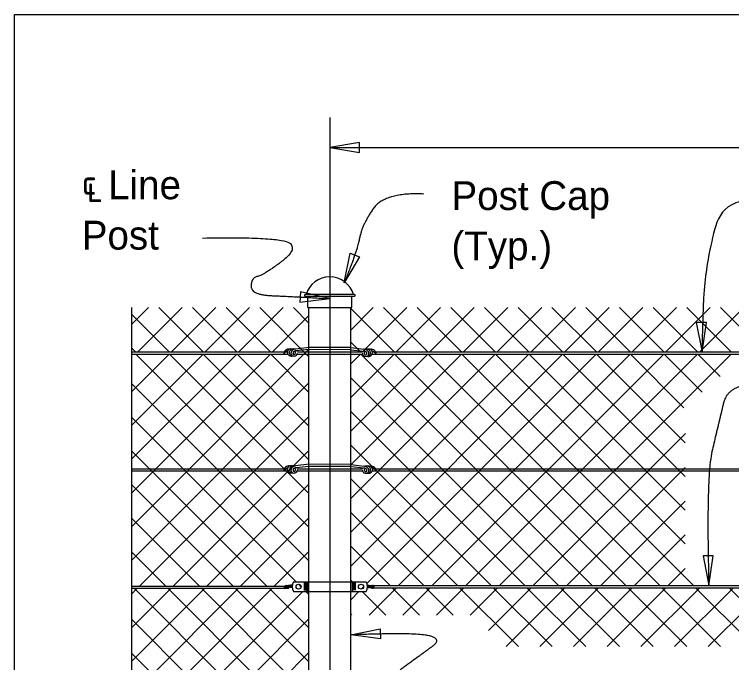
# Model space of a CAD drawing. Extents: x 0 to 41.1, y 0 to 26.4.
# Drawn here: x 0 to 5.02, y 21.87 to 26.4 of the extents above; entities that cross this region are included whole.
import ezdxf

# ---------------------------------------------------------------- set-up
doc = ezdxf.new("R2010")
doc.units = 0
for name, color, linetype in [('CL_Major', 7, 'Continuous'), ('Dimension', 7, 'Continuous'), ('Miscellaneous', 7, 'Continuous'), ('Miscellaneous1', 7, 'Continuous'), ('SteelMisc', 7, 'Continuous'), ('SteelMisc_h', 7, 'Continuous')]:
    doc.layers.add(name, color=color, linetype=linetype)

msp = doc.modelspace()

# ---------------------------------------------------------------- linework, layer by layer
at = {"layer": 'CL_Major'}
msp.add_line((2.2062, 25.6784), (2.2062, 14.8533), dxfattribs=at)
at = {"layer": 'Dimension'}
msp.add_line((2.2062, 25.4682), (22.2062, 25.4682), dxfattribs=at)
for points in [[(2.2062, 25.4682), (2.4145, 25.4329), (2.4145, 25.5035)], [(2.3061, 24.523), (2.3482, 24.73), (2.414, 24.7046)], [(2.2062, 24.4121), (2.0002, 24.4587), (1.9964, 24.3882)], [(4.8088, 24.0365), (4.8396, 24.2455), (4.769, 24.244)], [(4.8566, 22.4048), (4.8874, 22.6138), (4.8169, 22.6123)], [(2.3519, 22.0601), (2.5585, 22.1039), (2.5614, 22.0334)]]:
    msp.add_lwpolyline(points, close=True, dxfattribs=at)
msp.add_lwpolyline([(0.8194, 24.349), (0.8194, 21.1819), (0.9227, 21.1819), (0.8194, 21.1369), (0.716, 21.0919), (0.8194, 21.0919), (0.8194, 20.1983)], dxfattribs=at)
for points, degree in [([(2.8646, 25.1435), (2.5898, 25.1563), (2.4301, 24.926), (2.3965, 24.7387), (2.3061, 24.523)], 2), ([(5.2657, 25.0995), (4.9524, 25.1279), (4.8838, 24.8459), (4.8116, 24.5363), (4.8088, 24.0365)], 3), ([(1.3167, 24.8359), (1.8625, 24.8457), (1.9849, 24.7568), (1.7407, 24.5755), (1.6559, 24.5571), (1.6559, 24.4393), (1.9339, 24.427), (2.2062, 24.4121)], 2), ([(5.3115, 23.815), (4.9982, 23.8433), (4.9198, 23.5211), (4.8367, 23.1628), (4.8566, 22.4048)], 2), ([(3.2402, 21.7554), (3.0279, 21.7554), (2.6079, 21.7554), (2.8581, 21.9325), (2.9953, 22.0352), (2.7847, 22.0777), (2.352, 22.06)], 2)]:
    msp.add_open_spline(points, degree=degree, dxfattribs=at)
at = {"layer": 'Miscellaneous'}
for p, q in [((0.9371, 24.349), (0.8194, 24.2313)), ((1.1728, 24.349), (0.8602, 24.0365)), ((1.3218, 24.0365), (1.0093, 24.349)), ((1.4085, 24.349), (1.0959, 24.0365)), ((1.5575, 24.0365), (1.245, 24.349)), ((1.6442, 24.349), (1.3316, 24.0365)), ((1.7932, 24.0365), (1.4807, 24.349)), ((1.8799, 24.349), (1.5674, 24.0365)), ((2.0603, 24.0051), (1.7164, 24.349)), ((2.0603, 24.2408), (1.9521, 24.349)), ((2.658, 24.0365), (2.3455, 24.349)), ((2.509, 24.349), (2.352, 24.1921)), ((2.7447, 24.349), (2.4321, 24.0365)), ((2.8937, 24.0365), (2.5812, 24.349)), ((2.9804, 24.349), (2.6678, 24.0365)), ((3.1294, 24.0365), (2.8169, 24.349)), ((3.2161, 24.349), (2.9035, 24.0365)), ((3.3651, 24.0365), (3.0526, 24.349)), ((3.4518, 24.349), (3.1392, 24.0365)), ((3.6008, 24.0365), (3.2883, 24.349)), ((3.6875, 24.349), (3.3749, 24.0365)), ((3.8365, 24.0365), (3.524, 24.349)), ((3.9232, 24.349), (3.6106, 24.0365)), ((4.0722, 24.0365), (3.7597, 24.349)), ((4.1589, 24.349), (3.8463, 24.0365)), ((4.3079, 24.0365), (3.9954, 24.349)), ((4.3946, 24.349), (4.082, 24.0365)), ((4.5436, 24.0365), (4.2311, 24.349)), ((4.6303, 24.349), (4.3177, 24.0365)), ((4.7793, 24.0365), (4.4668, 24.349)), ((4.866, 24.349), (4.5535, 24.0365)), ((5.015, 24.0365), (4.7025, 24.349)), ((5.1017, 24.349), (4.7948, 24.0422)), ((5.2507, 24.0365), (4.9382, 24.349)), ((1.0861, 24.0365), (0.8194, 24.3033)), ((2.0603, 24.2938), (1.8031, 24.0365)), ((2.4223, 24.0365), (2.352, 24.1068)), ((2.0603, 24.0581), (0.8192, 22.817)), ((0.8504, 24.0365), (0.8194, 24.0676)), ((1.9047, 24.0365), (1.9002, 24.041)), ((1.7883, 24.0218), (0.8192, 23.0527)), ((1.5526, 24.0218), (0.8192, 23.2884)), ((1.3169, 24.0218), (0.8192, 23.5241)), ((1.0812, 24.0218), (0.8192, 23.7598)), ((2.0603, 22.8138), (0.8524, 24.0218)), ((2.0603, 23.0495), (1.0881, 24.0218)), ((2.0603, 23.2852), (1.3238, 24.0218)), ((2.0603, 23.5209), (1.5595, 24.0218)), ((2.0603, 23.7566), (1.7952, 24.0218)), ((3.8316, 24.0218), (2.352, 22.5421)), ((3.5959, 24.0218), (2.352, 22.7779)), ((3.3602, 24.0218), (2.352, 23.0136)), ((3.1245, 24.0218), (2.352, 23.2493)), ((2.8888, 24.0218), (2.352, 23.485)), ((2.6531, 24.0218), (2.352, 23.7207)), ((2.4174, 24.0218), (2.352, 23.9564)), ((4.0413, 22.4048), (2.4243, 24.0218)), ((4.0673, 24.0218), (2.4652, 22.4196)), ((4.277, 22.4048), (2.66, 24.0218)), ((4.303, 24.0218), (2.686, 22.4048)), ((4.5127, 22.4048), (2.8957, 24.0218)), ((4.5387, 24.0218), (2.9217, 22.4048)), ((4.7484, 22.4048), (3.1314, 24.0218)), ((4.7744, 24.0218), (3.1574, 22.4048)), ((4.6913, 22.6976), (3.3671, 24.0218)), ((5.0101, 24.0218), (3.3931, 22.4048)), ((4.6913, 22.9333), (3.6028, 24.0218)), ((4.6913, 23.169), (3.8385, 24.0218)), ((4.6913, 23.4047), (4.0742, 24.0218)), ((4.6827, 23.649), (4.3099, 24.0218)), ((4.8094, 23.758), (4.5456, 24.0218)), ((4.936, 23.8671), (4.7813, 24.0218)), ((3.8056, 22.4048), (2.352, 23.8583)), ((2.0603, 23.8224), (0.8192, 22.5813)), ((2.0603, 22.5781), (0.8194, 23.8191)), ((1.9708, 22.4319), (0.8194, 23.5834)), ((2.0603, 23.5867), (0.8745, 22.4009)), ((3.5699, 22.4048), (2.352, 23.6226)), ((4.6938, 23.4697), (3.6288, 22.4048)), ((3.3342, 22.4048), (2.352, 23.3869)), ((1.7662, 22.4009), (0.8194, 23.3477)), ((2.0603, 23.351), (1.1102, 22.4009)), ((4.6913, 23.2315), (3.8645, 22.4048)), ((1.9048, 23.219), (1.9004, 23.2235)), ((3.0985, 22.4048), (2.352, 23.1512)), ((1.5305, 22.4009), (0.8194, 23.112)), ((2.0603, 23.1153), (1.3459, 22.4009)), ((4.6913, 22.9958), (4.1002, 22.4048)), ((1.2948, 22.4009), (0.8194, 22.8763)), ((2.0603, 22.8796), (1.5816, 22.4009)), ((2.8628, 22.4048), (2.352, 22.9155)), ((4.6913, 22.7601), (4.3359, 22.4048)), ((2.6271, 22.4048), (2.352, 22.6798)), ((1.0591, 22.4009), (0.8194, 22.6406)), ((2.0603, 22.6439), (1.8173, 22.4009)), ((4.6913, 22.5244), (4.5716, 22.4048)), ((2.3642, 22.4319), (2.352, 22.4441)), ((0.8234, 22.4009), (0.8192, 22.405)), ((1.8028, 22.3863), (0.8192, 21.4028)), ((1.0955, 22.3862), (0.8192, 22.1099)), ((1.3313, 22.3862), (0.8192, 21.8742)), ((1.567, 22.3862), (0.8192, 21.6385)), ((0.8598, 22.3861), (0.8192, 22.3456)), ((2.0603, 21.1639), (0.8381, 22.3861)), ((2.0603, 21.3996), (1.0738, 22.3862)), ((2.0603, 21.6353), (1.3094, 22.3862)), ((2.0603, 21.871), (1.5451, 22.3862)), ((2.0559, 22.1112), (1.7808, 22.3863)), ((2.0058, 22.3969), (1.9883, 22.4144)), ((2.4419, 22.3963), (2.426, 22.3805)), ((2.6712, 22.39), (2.4806, 22.1994)), ((2.8325, 22.1994), (2.6418, 22.39)), ((2.9069, 22.39), (2.7163, 22.1994)), ((3.0682, 22.1994), (2.8775, 22.39)), ((3.1427, 22.39), (2.952, 22.1994)), ((3.5244, 21.9789), (3.1132, 22.39)), ((3.3784, 22.39), (3.1877, 22.1994)), ((3.6141, 22.39), (3.3156, 22.0916)), ((3.7601, 21.9789), (3.3489, 22.39)), ((3.8498, 22.39), (3.4386, 21.9789)), ((3.9958, 21.9789), (3.5846, 22.39)), ((4.0855, 22.39), (3.6743, 21.9789)), ((4.2315, 21.9789), (3.8203, 22.39)), ((4.3212, 22.39), (3.91, 21.9789)), ((4.4672, 21.9789), (4.056, 22.39)), ((4.5569, 22.39), (4.1457, 21.9789)), ((4.7029, 21.9789), (4.2917, 22.39)), ((4.7926, 22.39), (4.3814, 21.9789)), ((4.9386, 21.9789), (4.5274, 22.39)), ((5.0283, 22.39), (4.6171, 21.9789)), ((5.1743, 21.9789), (4.7631, 22.39)), ((5.264, 22.39), (4.8528, 21.9789)), ((7.2458, 20.143), (4.9988, 22.39)), ((2.0163, 22.3642), (0.8341, 21.1819)), ((2.0603, 22.3424), (2.0386, 22.3642)), ((2.4097, 22.3642), (2.352, 22.3064)), ((2.5968, 22.1994), (2.432, 22.3642)), ((2.0603, 22.1725), (0.8192, 20.9314)), ((2.3611, 22.1994), (2.352, 22.2084)), ((2.0603, 20.9282), (0.8192, 22.1693)), ((2.0603, 21.9368), (0.8192, 20.6957)), ((2.0603, 20.6925), (0.8192, 21.9336))]:
    msp.add_line(p, q, dxfattribs=at)
at = {"layer": 'Miscellaneous1'}
msp.add_lwpolyline([(0, 26.4), (41.0667, 26.4), (41.0667, 0), (0, 0)], close=True, dxfattribs=at)
at = {"layer": 'SteelMisc'}
for p, q in [((2.3786, 24.441), (2.0339, 24.441)), ((2.0339, 24.4288), (2.3786, 24.4288)), ((2.0521, 24.349), (2.0521, 24.4288)), ((2.3603, 24.349), (2.3603, 24.4288)), ((2.0521, 24.349), (2.3603, 24.349)), ((2.0603, 17.8646), (2.0603, 24.349)), ((2.352, 17.8646), (2.352, 24.349)), ((1.8858, 24.0365), (0.8192, 24.0365)), ((1.9095, 24.0365), (1.8943, 24.0365)), ((2.0608, 24.0708), (1.9665, 24.0597)), ((2.0608, 24.0563), (1.9686, 24.0469)), ((2.0603, 24.0365), (1.9799, 24.0365)), ((2.3519, 24.0691), (2.0608, 24.0708)), ((2.3519, 24.0546), (2.0608, 24.0563)), ((2.3519, 24.0691), (2.4468, 24.058)), ((2.3519, 24.0546), (2.4445, 24.0451)), ((2.4341, 24.0365), (2.3519, 24.0365)), ((2.5172, 24.0365), (2.504, 24.0365)), ((11.9229, 24.0365), (2.5271, 24.0365)), ((1.9144, 24.0218), (0.8192, 24.0218)), ((2.0603, 24.0218), (1.9772, 24.0218)), ((2.4355, 24.0218), (2.3519, 24.0218)), ((11.9243, 24.0218), (2.5005, 24.0218)), ((2.0609, 23.2533), (1.9666, 23.2422)), ((2.0609, 23.2388), (1.9688, 23.2294)), ((2.3521, 23.2516), (2.0609, 23.2533)), ((2.3521, 23.2371), (2.0609, 23.2388)), ((2.3521, 23.2516), (2.447, 23.2405)), ((2.3521, 23.2371), (2.4447, 23.2276)), ((1.886, 23.219), (0.8194, 23.219)), ((1.9146, 23.2043), (0.8194, 23.2043)), ((1.9097, 23.219), (1.8945, 23.219)), ((2.0604, 23.2043), (1.9774, 23.2043)), ((2.0604, 23.219), (1.98, 23.219)), ((2.4343, 23.219), (2.3521, 23.219)), ((2.4357, 23.2043), (2.3521, 23.2043)), ((11.9244, 23.2043), (2.5006, 23.2043)), ((2.5173, 23.219), (2.5042, 23.219)), ((11.9231, 23.219), (2.5273, 23.219)), ((1.9522, 22.4319), (2.4601, 22.4319)), ((2.0466, 22.3642), (2.0466, 22.4319)), ((2.0504, 22.3642), (2.0504, 22.4319)), ((2.3657, 22.3642), (2.3657, 22.4319)), ((0.8194, 22.4009), (1.8897, 22.4009)), ((0.8194, 22.3861), (1.916, 22.3863)), ((1.9443, 22.389), (1.9104, 22.3947)), ((1.9439, 22.3938), (1.9137, 22.3987)), ((1.9449, 22.4094), (1.9182, 22.405)), ((1.9442, 22.4044), (1.9182, 22.4002)), ((1.9352, 22.403), (1.9352, 22.3951)), ((2.0236, 22.4211), (2.0466, 22.4211)), ((2.0236, 22.4155), (2.0466, 22.4155)), ((2.0236, 22.4075), (2.0466, 22.4075)), ((2.0236, 22.402), (2.0466, 22.402)), ((2.0236, 22.394), (2.0466, 22.394)), ((2.0236, 22.3884), (2.0466, 22.3884)), ((2.0236, 22.3804), (2.0466, 22.3804)), ((2.0236, 22.3749), (2.0466, 22.3749)), ((2.3886, 22.4211), (2.3657, 22.4211)), ((2.3886, 22.4155), (2.3657, 22.4155)), ((2.3886, 22.4075), (2.3657, 22.4075)), ((2.3886, 22.402), (2.3657, 22.402)), ((2.3886, 22.394), (2.3657, 22.394)), ((2.3886, 22.3884), (2.3657, 22.3884)), ((2.3886, 22.3804), (2.3657, 22.3804)), ((2.3886, 22.3749), (2.3657, 22.3749)), ((2.4674, 22.4094), (2.4967, 22.4048)), ((2.468, 22.389), (2.5017, 22.3946)), ((2.4681, 22.4044), (2.4942, 22.4003)), ((2.4684, 22.3937), (2.4983, 22.3987)), ((2.477, 22.4029), (2.477, 22.3951)), ((2.5108, 22.4048), (11.8852, 22.4048)), ((2.5141, 22.39), (11.9118, 22.39)), ((1.9524, 22.3642), (2.4597, 22.3642))]:
    msp.add_line(p, q, dxfattribs=at)
for centre, start, end in [((2.034, 24.4347), 91.1647, 268.8353), ((2.3783, 24.4347), 271.1647, 88.8353)]:
    msp.add_arc(centre, 0.00613, start, end, dxfattribs=at)
for centre, major_axis, ratio, start_param, end_param in [((2.2054, 24.4), (-0.1711, 0), 0.957868, 3.394611, 6.030583), ((1.9208, 24.024), (0.0373, 0), 0.957868, 1.486836, 3.108042), ((1.9419, 23.9843), (-0.0724, 0), 0.957868, 5.162149, 5.652106), ((1.9344, 24.036), (-0.0249, 0), 0.957868, 6.009018, 7.089857), ((1.9333, 24.0385), (0.023, 0), 0.957868, 1.29026, 2.970541), ((1.952, 24.0331), (0.0295, 0), 0.957868, 1.220941, 4.039556), ((1.9655, 24.0349), (-0.0303, -0.0108), 0.724765, 4.35367, 6.324556), ((1.9622, 24.0308), (-0.0139, 0), 0.957868, 5.22362, 6.905413), ((1.9565, 24.0284), (-0.00795, 0), 0.957868, 6.140374, 9.314262), ((1.9706, 24.022), (-0.0259, 0), 0.957868, 4.777514, 5.62749), ((1.9548, 24.0342), (0.0119, 0), 0.957868, 5.725876, 7.416677), ((1.9548, 24.0342), (0.0119, 0), 0.957868, 5.639684, 5.723117), ((1.9551, 24.033), (0.0251, 0), 0.957868, 5.531357, 6.227833), ((1.9551, 24.033), (0.0251, 0), 0.957868, 0.407687, 0.609214), ((2.4586, 24.0312), (-0.0251, 0), 0.957868, 0.055352, 0.751829), ((2.4586, 24.0312), (-0.0251, 0), 0.957868, 5.673972, 5.875498), ((2.4481, 24.0331), (0.0303, -0.0108), 0.724765, 6.241815, 8.212701), ((2.4431, 24.0202), (0.0259, 0), 0.957868, 0.655696, 1.505671), ((2.4588, 24.0325), (-0.0119, 0), 0.957868, 5.149694, 6.840495), ((2.4571, 24.0267), (0.00795, 0), 0.957868, 3.252108, 6.425997), ((2.4616, 24.0313), (-0.0295, 0), 0.957868, 2.243629, 5.062245), ((2.4514, 24.029), (0.0139, 0), 0.957868, 5.660958, 7.342751), ((2.4803, 24.0367), (-0.023, 0), 0.957868, 3.312645, 4.992926), ((2.4928, 24.0222), (-0.0373, 0), 0.957868, 3.175144, 4.79635), ((2.4792, 24.0342), (0.0249, 0), 0.957868, 5.476514, 6.557353), ((2.4717, 23.9825), (0.0724, 0), 0.957868, 0.631079, 1.121037), ((1.9358, 24.032), (0.0231, 0), 0.957868, 3.779554, 4.879821), ((1.9419, 24.0263), (0.0206, -0.0021), 0.798607, 4.32653, 5.220153), ((1.9554, 24.0263), (0.0206, -0.0021), 0.798607, 3.333154, 5.220153), ((1.948, 24.045), (0.0391, 0), 0.957868, 5.082588, 5.41974), ((2.4656, 24.0433), (-0.0391, 0), 0.957868, 0.863445, 1.200597), ((2.4588, 24.0325), (-0.0119, 0), 0.957868, 0.560069, 0.643501), ((2.4582, 24.0245), (-0.0206, -0.0021), 0.798607, 1.063032, 2.950031), ((2.4717, 24.0245), (-0.0206, -0.0021), 0.798607, 1.063032, 1.956656), ((2.4778, 24.0302), (-0.0231, 0), 0.957868, 1.403365, 2.503632), ((1.921, 23.2065), (0.0373, 0), 0.957868, 1.486836, 3.108042), ((1.9421, 23.1668), (-0.0724, 0), 0.957868, 5.162149, 5.652106), ((1.9346, 23.2185), (-0.0249, 0), 0.957868, 6.009018, 7.089857), ((1.9335, 23.221), (0.023, 0), 0.957868, 1.29026, 2.970541), ((1.9522, 23.2156), (0.0295, 0), 0.957868, 1.220941, 4.039556), ((1.9657, 23.2174), (-0.0303, -0.0108), 0.724765, 4.35367, 6.324556), ((1.9624, 23.2134), (-0.0139, 0), 0.957868, 5.22362, 6.905413), ((1.9707, 23.2045), (-0.0259, 0), 0.957868, 4.777514, 5.62749), ((1.955, 23.2168), (0.0119, 0), 0.957868, 5.725876, 7.416677), ((1.9552, 23.2155), (0.0251, 0), 0.957868, 0.407687, 0.609214), ((2.4588, 23.2138), (-0.0251, 0), 0.957868, 5.673972, 5.875498), ((2.4433, 23.2027), (0.0259, 0), 0.957868, 0.655696, 1.505671), ((2.4483, 23.2157), (0.0303, -0.0108), 0.724765, 6.241815, 8.212701), ((2.459, 23.215), (-0.0119, 0), 0.957868, 5.149694, 6.840495), ((2.4618, 23.2139), (-0.0295, 0), 0.957868, 2.243629, 5.062245), ((2.4805, 23.2192), (-0.023, 0), 0.957868, 3.312645, 4.992926), ((2.493, 23.2048), (-0.0373, 0), 0.957868, 3.175144, 4.79635), ((2.4719, 23.1651), (0.0724, 0), 0.957868, 0.631079, 1.121037), ((1.936, 23.2145), (0.0231, 0), 0.957868, 3.779554, 4.879821), ((1.9421, 23.2088), (0.0206, -0.0021), 0.798607, 4.32653, 5.220153), ((1.9556, 23.2088), (0.0206, -0.0021), 0.798607, 3.333154, 5.220153), ((1.9567, 23.211), (-0.00795, 0), 0.957868, 6.140374, 9.314262), ((1.9482, 23.2276), (0.0391, 0), 0.957868, 5.082588, 5.41974), ((1.955, 23.2168), (0.0119, 0), 0.957868, 5.639684, 5.723117), ((1.9552, 23.2155), (0.0251, 0), 0.957868, 5.531357, 6.227833), ((2.4588, 23.2138), (-0.0251, 0), 0.957868, 0.055352, 0.751829), ((2.4658, 23.2258), (-0.0391, 0), 0.957868, 0.863445, 1.200597), ((2.459, 23.215), (-0.0119, 0), 0.957868, 0.560069, 0.643501), ((2.4573, 23.2092), (0.00795, 0), 0.957868, 3.252108, 6.425997), ((2.4584, 23.207), (-0.0206, -0.0021), 0.798607, 1.063032, 2.950031), ((2.4516, 23.2116), (0.0139, 0), 0.957868, 5.660958, 7.342751), ((2.4719, 23.207), (-0.0206, -0.0021), 0.798607, 1.063032, 1.956656), ((2.478, 23.2127), (-0.0231, 0), 0.957868, 1.403365, 2.503632), ((2.4794, 23.2167), (0.0249, 0), 0.957868, 5.476514, 6.557353), ((2.0214, 22.3983), (-0.0776, 0), 0.957868, 5.81433, 6.762456), ((2.3908, 22.3983), (0.0776, 0), 0.957868, 5.803915, 6.752041), ((1.9, 22.3915), (0.0142, 0), 0.957868, 1.427866, 3.10804), ((1.908, 22.3765), (-0.0274, 0), 0.957868, 5.133531, 5.652105), ((1.9052, 22.3961), (-0.00944, 0), 0.957868, 5.913863, 8.247076), ((1.9047, 22.397), (0.00872, 0), 0.957868, 1.103089, 2.861068), ((1.9047, 22.397), (0.00503, 0), 0.92697, 1.632124, 4.493683), ((1.9113, 22.3965), (0.00872, 0), 0.957868, 1.202886, 4.168248), ((1.9169, 22.3957), (-0.0115, -0.0041), 0.737732, 4.35367, 7.518104), ((1.9157, 22.3941), (-0.00527, 0), 0.957868, 5.822913, 6.90541), ((1.9135, 22.3932), (-0.00301, 0), 0.957868, 5.79353, 6.278592), ((1.9189, 22.3908), (-0.00982, 0), 0.957868, 4.777514, 5.64637), ((1.9135, 22.3932), (-0.00301, 0), 0.957868, 0.785393, 3.285656), ((1.9129, 22.3954), (0.00453, 0), 0.957868, 0.731188, 1.133458), ((1.913, 22.3949), (0.0095, 0), 0.957868, 5.036011, 6.030719), ((1.913, 22.3949), (0.0095, 0), 0.957868, 0.267283, 0.659981), ((2.4993, 22.3949), (-0.0095, 0), 0.957868, 5.673972, 6.052579), ((2.4993, 22.3949), (-0.0095, 0), 0.957868, 0.252467, 1.271421), ((2.4934, 22.3908), (0.00982, 0), 0.957868, 0.655696, 1.505671), ((2.4953, 22.3957), (0.0115, -0.0041), 0.737732, 5.08821, 8.212701), ((2.4987, 22.3932), (0.00301, 0), 0.957868, 3.28349, 5.170635), ((2.4993, 22.3954), (-0.00453, 0), 0.957868, 5.149727, 5.551998), ((2.4966, 22.3941), (0.00527, 0), 0.957868, 5.058829, 7.342751), ((2.501, 22.3965), (-0.00872, 0), 0.957868, 2.1008, 4.992926), ((2.4987, 22.3932), (0.00301, 0), 0.957868, 0.004594, 0.141897), ((2.5071, 22.3961), (0.00944, 0), 0.957868, 4.316497, 6.557353), ((2.5075, 22.397), (-0.00872, 0), 0.957868, 3.323334, 4.992926), ((2.5075, 22.397), (-0.00503, 0), 0.92697, 1.780895, 4.712389)]:
    msp.add_ellipse(centre, major_axis=major_axis, ratio=ratio, start_param=start_param, end_param=end_param, dxfattribs=at)
for centre, major_axis in [((1.9881, 22.3974), (0.0178, 0)), ((2.4241, 22.3974), (-0.0178, 0))]:
    msp.add_ellipse(centre, major_axis=major_axis, ratio=0.957868, dxfattribs=at)
at = {"layer": 'SteelMisc_h'}
for p, q in [((2.3519, 24.0365), (2.0603, 24.0365)), ((2.3519, 24.0218), (2.0603, 24.0218)), ((2.3521, 23.219), (2.0604, 23.219)), ((2.3521, 23.2043), (2.0604, 23.2043))]:
    msp.add_line(p, q, dxfattribs=at)

# ---------------------------------------------------------------- texts
at = {"layer": 'Dimension'}
for s, p in [('℄ Line ', (0.4713, 25.1069)), ('Post Cap ', (3.0566, 25.0317)), ('Post', (0.4713, 24.7549)), ('(Typ.)', (3.0566, 24.6797))]:
    msp.add_text(s, height=0.2016, dxfattribs=at).set_placement(p)

doc.saveas('drawing.dxf')
